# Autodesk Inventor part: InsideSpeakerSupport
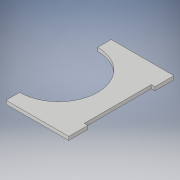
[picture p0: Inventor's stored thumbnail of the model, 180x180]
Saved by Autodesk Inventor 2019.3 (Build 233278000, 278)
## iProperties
Created: 2020-02
Part Number: InsideSpeakerSupport
Material: Generic
Document SubType Name: Modeling
Designer: KrystynWikoff
Density: 1 g/cm^3
Appearance: Default
Author: KrystynWikoff
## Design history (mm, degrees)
sketch "Sketch1"
  geometry: L1 (0, 0)-(41.732, 0); L2 (41.732, 0)-(41.732, -70); L3 (41.732, -70)-(0, -70); L4 (0, -70)-(0, 0)
  constraints: 8 end point, 2 parallel, 1 horizontal, 1 perpendicular
  dimensions: "d0" = 70 distance of L3.end L1.start; "d1" = 41.7322 distance of L1.start L1.end
extrude "Extrusion1" new body sketch "Sketch1" distance "d2" = 2.3622; taper "d3" = 0 deg
sketch "Sketch2"
  geometry: L1 (-41.732, 70)-(-41.732, 0) reference; L2 (-41.732, 0)-(0, 0) reference; L3 (0, 0)-(0, 70) reference; L4 (0, 12.7)-(-2.362, 12.7); L5 (-2.362, 12.7)-(-2.362, 57.3); L6 (-2.362, 57.3)-(0, 57.3); L7 (0, 57.3)-(0, 12.7); L8 (0, 70)-(-41.732, 70) reference; C1 r 26 at (-41.732, 35)
  constraints: 8 end point, 2 parallel, 1 centre point, 1 horizontal, 1 midpoint, 1 perpendicular, 1 point on line
  dimensions: "d4" = 35 distance from line of L2 C1.centre; "d5" = 52 diameter of C1; "d6" = 12.7 distance between parallel lines of L2 L4; "d7" = 2.3622 distance of L5.end L6.end; "d8" = 12.7 distance between parallel lines of L8 L6
extrude "Extrusion2" cut sketch "Sketch2" distance "d9" = 2.3622; taper "d10" = 0 deg
body "Solid1"
